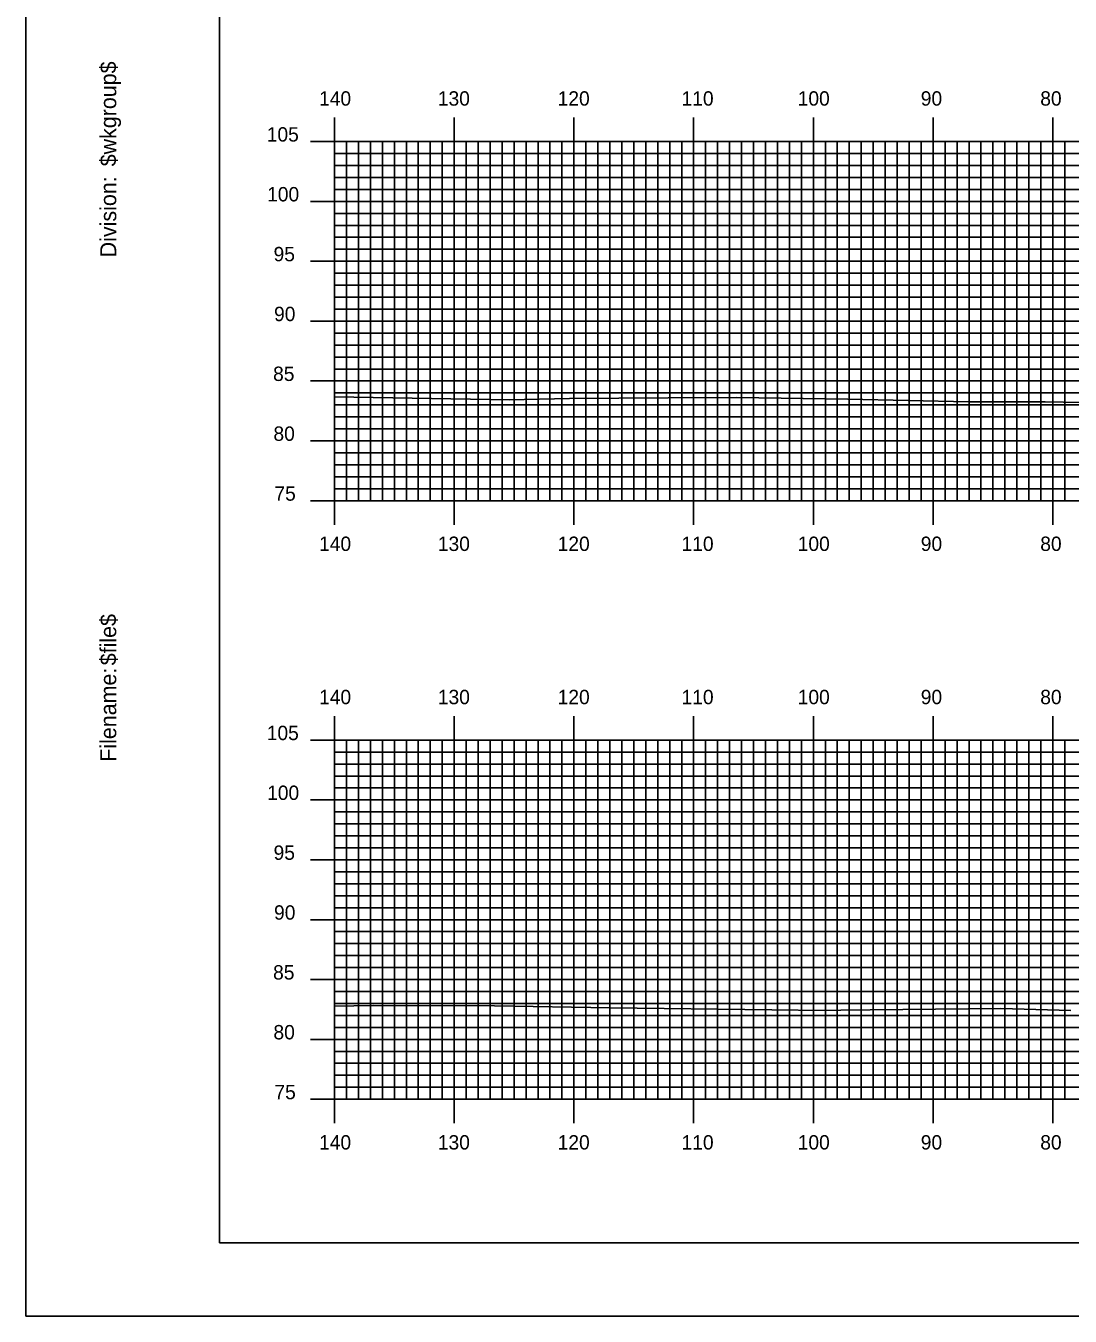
# Model space of a CAD drawing. Extents: x 1757856 to 1758199, y 442591 to 442811.
# Drawn here: x 1757855.8 to 1757943.1, y 442590.5 to 442698.3 of the extents above; entities that cross this region are included whole.
import ezdxf

# ---------------------------------------------------------------- set-up
doc = ezdxf.new("R2010")
doc.units = 0
for name, color, linetype in [('BORDER', 7, 'Continuous'), ('H_V ANNOTATION', 7, 'Continuous'), ('MAJOR', 7, 'Continuous'), ('MINOR', 7, 'Continuous'), ('PLOT BOUNDARY', 7, 'Continuous'), ('S_Roadway_Centerline', 7, 'Continuous')]:
    doc.layers.add(name, color=color, linetype=linetype)

msp = doc.modelspace()

# ---------------------------------------------------------------- linework, layer by layer
at = {"layer": 'BORDER'}
msp.add_lwpolyline([(1757872.02, 442596.67), (1758192.02, 442596.67), (1758192.02, 442806.67), (1757872.02, 442806.67)], close=True, dxfattribs=at)
at = {"layer": 'MAJOR'}
for p, q in [((1757881.62, 442690.67), (1757881.62, 442688.67)), ((1757891.62, 442690.67), (1757891.62, 442688.67)), ((1757901.62, 442690.67), (1757901.62, 442688.67)), ((1757911.62, 442690.67), (1757911.62, 442688.67)), ((1757921.62, 442690.67), (1757921.62, 442688.67)), ((1757931.62, 442690.67), (1757931.62, 442688.67)), ((1757941.62, 442690.67), (1757941.62, 442688.67)), ((1757879.62, 442688.67), (1757881.62, 442688.67)), ((1757881.62, 442688.67), (1758161.62, 442688.67)), ((1757881.62, 442658.67), (1757881.62, 442688.67)), ((1757881.62, 442658.67), (1757881.62, 442688.67)), ((1757881.62, 442688.67), (1758161.62, 442688.67)), ((1757891.62, 442658.67), (1757891.62, 442688.67)), ((1757901.62, 442658.67), (1757901.62, 442688.67)), ((1757911.62, 442658.67), (1757911.62, 442688.67)), ((1757921.62, 442658.67), (1757921.62, 442688.67)), ((1757931.62, 442658.67), (1757931.62, 442688.67)), ((1757941.62, 442658.67), (1757941.62, 442688.67)), ((1757879.62, 442683.67), (1757881.62, 442683.67)), ((1757881.62, 442683.67), (1758161.62, 442683.67)), ((1757879.62, 442678.67), (1757881.62, 442678.67)), ((1757881.62, 442678.67), (1758161.62, 442678.67)), ((1757879.62, 442673.67), (1757881.62, 442673.67)), ((1757881.62, 442673.67), (1758161.62, 442673.67)), ((1757879.62, 442668.67), (1757881.62, 442668.67)), ((1757881.62, 442668.67), (1758161.62, 442668.67)), ((1757879.62, 442663.67), (1757881.62, 442663.67)), ((1757881.62, 442663.67), (1758161.62, 442663.67)), ((1757879.62, 442658.67), (1757881.62, 442658.67)), ((1757881.62, 442658.67), (1758161.62, 442658.67)), ((1757881.62, 442658.67), (1758161.62, 442658.67)), ((1757881.62, 442656.66), (1757881.62, 442658.67)), ((1757891.62, 442656.66), (1757891.62, 442658.67)), ((1757901.62, 442656.66), (1757901.62, 442658.67)), ((1757911.62, 442656.66), (1757911.62, 442658.67)), ((1757921.62, 442656.66), (1757921.62, 442658.67)), ((1757931.62, 442656.66), (1757931.62, 442658.67)), ((1757941.62, 442656.66), (1757941.62, 442658.67)), ((1757881.62, 442640.67), (1757881.62, 442638.67)), ((1757891.62, 442640.67), (1757891.62, 442638.67)), ((1757901.62, 442640.67), (1757901.62, 442638.67)), ((1757911.62, 442640.67), (1757911.62, 442638.67)), ((1757921.62, 442640.67), (1757921.62, 442638.67)), ((1757931.62, 442640.67), (1757931.62, 442638.67)), ((1757941.62, 442640.67), (1757941.62, 442638.67)), ((1757879.62, 442638.67), (1757881.62, 442638.67)), ((1757881.62, 442638.67), (1758161.62, 442638.67)), ((1757881.62, 442608.67), (1757881.62, 442638.67)), ((1757881.62, 442608.67), (1757881.62, 442638.67)), ((1757881.62, 442638.67), (1758161.62, 442638.67)), ((1757891.62, 442608.67), (1757891.62, 442638.67)), ((1757901.62, 442608.67), (1757901.62, 442638.67)), ((1757911.62, 442608.67), (1757911.62, 442638.67)), ((1757921.62, 442608.67), (1757921.62, 442638.67)), ((1757931.62, 442608.67), (1757931.62, 442638.67)), ((1757941.62, 442608.67), (1757941.62, 442638.67)), ((1757879.62, 442633.67), (1757881.62, 442633.67)), ((1757881.62, 442633.67), (1758161.62, 442633.67)), ((1757879.62, 442628.67), (1757881.62, 442628.67)), ((1757881.62, 442628.67), (1758161.62, 442628.67)), ((1757879.62, 442623.67), (1757881.62, 442623.67)), ((1757881.62, 442623.67), (1758161.62, 442623.67)), ((1757879.62, 442618.67), (1757881.62, 442618.67)), ((1757881.62, 442618.67), (1758161.62, 442618.67)), ((1757879.62, 442613.67), (1757881.62, 442613.67)), ((1757881.62, 442613.67), (1758161.62, 442613.67)), ((1757879.62, 442608.67), (1757881.62, 442608.67)), ((1757881.62, 442608.67), (1758161.62, 442608.67)), ((1757881.62, 442608.67), (1758161.62, 442608.67)), ((1757881.62, 442606.66), (1757881.62, 442608.67)), ((1757891.62, 442606.66), (1757891.62, 442608.67)), ((1757901.62, 442606.66), (1757901.62, 442608.67)), ((1757911.62, 442606.66), (1757911.62, 442608.67)), ((1757921.62, 442606.66), (1757921.62, 442608.67)), ((1757931.62, 442606.66), (1757931.62, 442608.67)), ((1757941.62, 442606.66), (1757941.62, 442608.67))]:
    msp.add_line(p, q, dxfattribs=at)
at = {"layer": 'MINOR'}
for p, q in [((1757882.62, 442658.67), (1757882.62, 442688.67)), ((1757883.62, 442658.67), (1757883.62, 442688.67)), ((1757884.62, 442658.67), (1757884.62, 442688.67)), ((1757885.62, 442658.67), (1757885.62, 442688.67)), ((1757886.62, 442658.67), (1757886.62, 442688.67)), ((1757887.62, 442658.67), (1757887.62, 442688.67)), ((1757888.62, 442658.67), (1757888.62, 442688.67)), ((1757889.62, 442658.67), (1757889.62, 442688.67)), ((1757890.62, 442658.67), (1757890.62, 442688.67)), ((1757892.62, 442658.67), (1757892.62, 442688.67)), ((1757893.62, 442658.67), (1757893.62, 442688.67)), ((1757894.62, 442658.67), (1757894.62, 442688.67)), ((1757895.62, 442658.67), (1757895.62, 442688.67)), ((1757896.62, 442658.67), (1757896.62, 442688.67)), ((1757897.62, 442658.67), (1757897.62, 442688.67)), ((1757898.62, 442658.67), (1757898.62, 442688.67)), ((1757899.62, 442658.67), (1757899.62, 442688.67)), ((1757900.62, 442658.67), (1757900.62, 442688.67)), ((1757902.62, 442658.67), (1757902.62, 442688.67)), ((1757903.62, 442658.67), (1757903.62, 442688.67)), ((1757904.62, 442658.67), (1757904.62, 442688.67)), ((1757905.62, 442658.67), (1757905.62, 442688.67)), ((1757906.62, 442658.67), (1757906.62, 442688.67)), ((1757907.62, 442658.67), (1757907.62, 442688.67)), ((1757908.62, 442658.67), (1757908.62, 442688.67)), ((1757909.62, 442658.67), (1757909.62, 442688.67)), ((1757910.62, 442658.67), (1757910.62, 442688.67)), ((1757912.62, 442658.67), (1757912.62, 442688.67)), ((1757913.62, 442658.67), (1757913.62, 442688.67)), ((1757914.62, 442658.67), (1757914.62, 442688.67)), ((1757915.62, 442658.67), (1757915.62, 442688.67)), ((1757916.62, 442658.67), (1757916.62, 442688.67)), ((1757917.62, 442658.67), (1757917.62, 442688.67)), ((1757918.62, 442658.67), (1757918.62, 442688.67)), ((1757919.62, 442658.67), (1757919.62, 442688.67)), ((1757920.62, 442658.67), (1757920.62, 442688.67)), ((1757922.62, 442658.67), (1757922.62, 442688.67)), ((1757923.62, 442658.67), (1757923.62, 442688.67)), ((1757924.62, 442658.67), (1757924.62, 442688.67)), ((1757925.62, 442658.67), (1757925.62, 442688.67)), ((1757926.62, 442658.67), (1757926.62, 442688.67)), ((1757927.62, 442658.67), (1757927.62, 442688.67)), ((1757928.62, 442658.67), (1757928.62, 442688.67)), ((1757929.62, 442658.67), (1757929.62, 442688.67)), ((1757930.62, 442658.67), (1757930.62, 442688.67)), ((1757932.62, 442658.67), (1757932.62, 442688.67)), ((1757933.62, 442658.67), (1757933.62, 442688.67)), ((1757934.62, 442658.67), (1757934.62, 442688.67)), ((1757935.62, 442658.67), (1757935.62, 442688.67)), ((1757936.62, 442658.67), (1757936.62, 442688.67)), ((1757937.62, 442658.67), (1757937.62, 442688.67)), ((1757938.62, 442658.67), (1757938.62, 442688.67)), ((1757939.62, 442658.67), (1757939.62, 442688.67)), ((1757940.62, 442658.67), (1757940.62, 442688.67)), ((1757942.62, 442658.67), (1757942.62, 442688.67)), ((1757881.62, 442687.67), (1758161.62, 442687.67)), ((1757881.62, 442687.67), (1757883.63, 442687.67)), ((1757881.62, 442686.67), (1758161.62, 442686.67)), ((1757881.62, 442686.67), (1757883.63, 442686.67)), ((1757881.62, 442685.67), (1758161.62, 442685.67)), ((1757881.62, 442685.67), (1757883.63, 442685.67)), ((1757881.62, 442684.67), (1758161.62, 442684.67)), ((1757881.62, 442684.67), (1757883.63, 442684.67)), ((1757881.62, 442682.67), (1758161.62, 442682.67)), ((1757881.62, 442682.67), (1757883.63, 442682.67)), ((1757881.62, 442681.67), (1758161.62, 442681.67)), ((1757881.62, 442681.67), (1757883.63, 442681.67)), ((1757881.62, 442680.67), (1758161.62, 442680.67)), ((1757881.62, 442680.67), (1757883.63, 442680.67)), ((1757881.62, 442679.67), (1758161.62, 442679.67)), ((1757881.62, 442679.67), (1757883.63, 442679.67)), ((1757881.62, 442677.67), (1758161.62, 442677.67)), ((1757881.62, 442677.67), (1757883.63, 442677.67)), ((1757881.62, 442676.67), (1758161.62, 442676.67)), ((1757881.62, 442676.67), (1757883.63, 442676.67)), ((1757881.62, 442675.67), (1758161.62, 442675.67)), ((1757881.62, 442675.67), (1757883.63, 442675.67)), ((1757881.62, 442674.67), (1758161.62, 442674.67)), ((1757881.62, 442674.67), (1757883.63, 442674.67)), ((1757881.62, 442672.67), (1758161.62, 442672.67)), ((1757881.62, 442672.67), (1757883.63, 442672.67)), ((1757881.62, 442671.67), (1758161.62, 442671.67)), ((1757881.62, 442671.67), (1757883.63, 442671.67)), ((1757881.62, 442670.67), (1758161.62, 442670.67)), ((1757881.62, 442670.67), (1757883.63, 442670.67)), ((1757881.62, 442669.67), (1758161.62, 442669.67)), ((1757881.62, 442669.67), (1757883.63, 442669.67)), ((1757881.62, 442667.67), (1758161.62, 442667.67)), ((1757881.62, 442667.67), (1757883.63, 442667.67)), ((1757881.62, 442666.67), (1758161.62, 442666.67)), ((1757881.62, 442666.67), (1757883.63, 442666.67)), ((1757881.62, 442665.67), (1758161.62, 442665.67)), ((1757881.62, 442665.67), (1757883.63, 442665.67)), ((1757881.62, 442664.67), (1758161.62, 442664.67)), ((1757881.62, 442664.67), (1757883.63, 442664.67)), ((1757881.62, 442662.67), (1758161.62, 442662.67)), ((1757881.62, 442662.67), (1757883.63, 442662.67)), ((1757881.62, 442661.67), (1758161.62, 442661.67)), ((1757881.62, 442661.67), (1757883.63, 442661.67)), ((1757881.62, 442660.67), (1758161.62, 442660.67)), ((1757881.62, 442660.67), (1757883.63, 442660.67)), ((1757881.62, 442659.67), (1758161.62, 442659.67)), ((1757881.62, 442659.67), (1757883.63, 442659.67)), ((1757882.62, 442608.67), (1757882.62, 442638.67)), ((1757883.62, 442608.67), (1757883.62, 442638.67)), ((1757884.62, 442608.67), (1757884.62, 442638.67)), ((1757885.62, 442608.67), (1757885.62, 442638.67)), ((1757886.62, 442608.67), (1757886.62, 442638.67)), ((1757887.62, 442608.67), (1757887.62, 442638.67)), ((1757888.62, 442608.67), (1757888.62, 442638.67)), ((1757889.62, 442608.67), (1757889.62, 442638.67)), ((1757890.62, 442608.67), (1757890.62, 442638.67)), ((1757892.62, 442608.67), (1757892.62, 442638.67)), ((1757893.62, 442608.67), (1757893.62, 442638.67)), ((1757894.62, 442608.67), (1757894.62, 442638.67)), ((1757895.62, 442608.67), (1757895.62, 442638.67)), ((1757896.62, 442608.67), (1757896.62, 442638.67)), ((1757897.62, 442608.67), (1757897.62, 442638.67)), ((1757898.62, 442608.67), (1757898.62, 442638.67)), ((1757899.62, 442608.67), (1757899.62, 442638.67)), ((1757900.62, 442608.67), (1757900.62, 442638.67)), ((1757902.62, 442608.67), (1757902.62, 442638.67)), ((1757903.62, 442608.67), (1757903.62, 442638.67)), ((1757904.62, 442608.67), (1757904.62, 442638.67)), ((1757905.62, 442608.67), (1757905.62, 442638.67)), ((1757906.62, 442608.67), (1757906.62, 442638.67)), ((1757907.62, 442608.67), (1757907.62, 442638.67)), ((1757908.62, 442608.67), (1757908.62, 442638.67)), ((1757909.62, 442608.67), (1757909.62, 442638.67)), ((1757910.62, 442608.67), (1757910.62, 442638.67)), ((1757912.62, 442608.67), (1757912.62, 442638.67)), ((1757913.62, 442608.67), (1757913.62, 442638.67)), ((1757914.62, 442608.67), (1757914.62, 442638.67)), ((1757915.62, 442608.67), (1757915.62, 442638.67)), ((1757916.62, 442608.67), (1757916.62, 442638.67)), ((1757917.62, 442608.67), (1757917.62, 442638.67)), ((1757918.62, 442608.67), (1757918.62, 442638.67)), ((1757919.62, 442608.67), (1757919.62, 442638.67)), ((1757920.62, 442608.67), (1757920.62, 442638.67)), ((1757922.62, 442608.67), (1757922.62, 442638.67)), ((1757923.62, 442608.67), (1757923.62, 442638.67)), ((1757924.62, 442608.67), (1757924.62, 442638.67)), ((1757925.62, 442608.67), (1757925.62, 442638.67)), ((1757926.62, 442608.67), (1757926.62, 442638.67)), ((1757927.62, 442608.67), (1757927.62, 442638.67)), ((1757928.62, 442608.67), (1757928.62, 442638.67)), ((1757929.62, 442608.67), (1757929.62, 442638.67)), ((1757930.62, 442608.67), (1757930.62, 442638.67)), ((1757932.62, 442608.67), (1757932.62, 442638.67)), ((1757933.62, 442608.67), (1757933.62, 442638.67)), ((1757934.62, 442608.67), (1757934.62, 442638.67)), ((1757935.62, 442608.67), (1757935.62, 442638.67)), ((1757936.62, 442608.67), (1757936.62, 442638.67)), ((1757937.62, 442608.67), (1757937.62, 442638.67)), ((1757938.62, 442608.67), (1757938.62, 442638.67)), ((1757939.62, 442608.67), (1757939.62, 442638.67)), ((1757940.62, 442608.67), (1757940.62, 442638.67)), ((1757942.62, 442608.67), (1757942.62, 442638.67)), ((1757881.62, 442637.67), (1758161.62, 442637.67)), ((1757881.62, 442637.67), (1757883.63, 442637.67)), ((1757881.62, 442636.67), (1758161.62, 442636.67)), ((1757881.62, 442636.67), (1757883.63, 442636.67)), ((1757881.62, 442635.67), (1758161.62, 442635.67)), ((1757881.62, 442635.67), (1757883.63, 442635.67)), ((1757881.62, 442634.67), (1758161.62, 442634.67)), ((1757881.62, 442634.67), (1757883.63, 442634.67)), ((1757881.62, 442632.67), (1758161.62, 442632.67)), ((1757881.62, 442632.67), (1757883.63, 442632.67)), ((1757881.62, 442631.67), (1758161.62, 442631.67)), ((1757881.62, 442631.67), (1757883.63, 442631.67)), ((1757881.62, 442630.67), (1758161.62, 442630.67)), ((1757881.62, 442630.67), (1757883.63, 442630.67)), ((1757881.62, 442629.67), (1758161.62, 442629.67)), ((1757881.62, 442629.67), (1757883.63, 442629.67)), ((1757881.62, 442627.67), (1758161.62, 442627.67)), ((1757881.62, 442627.67), (1757883.63, 442627.67)), ((1757881.62, 442626.67), (1758161.62, 442626.67)), ((1757881.62, 442626.67), (1757883.63, 442626.67)), ((1757881.62, 442625.67), (1758161.62, 442625.67)), ((1757881.62, 442625.67), (1757883.63, 442625.67)), ((1757881.62, 442624.67), (1758161.62, 442624.67)), ((1757881.62, 442624.67), (1757883.63, 442624.67)), ((1757881.62, 442622.67), (1758161.62, 442622.67)), ((1757881.62, 442622.67), (1757883.63, 442622.67)), ((1757881.62, 442621.67), (1758161.62, 442621.67)), ((1757881.62, 442621.67), (1757883.63, 442621.67)), ((1757881.62, 442620.67), (1758161.62, 442620.67)), ((1757881.62, 442620.67), (1757883.63, 442620.67)), ((1757881.62, 442619.67), (1758161.62, 442619.67)), ((1757881.62, 442619.67), (1757883.63, 442619.67)), ((1757881.62, 442617.67), (1758161.62, 442617.67)), ((1757881.62, 442617.67), (1757883.63, 442617.67)), ((1757881.62, 442616.67), (1758161.62, 442616.67)), ((1757881.62, 442616.67), (1757883.63, 442616.67)), ((1757881.62, 442615.67), (1758161.62, 442615.67)), ((1757881.62, 442615.67), (1757883.63, 442615.67)), ((1757881.62, 442614.67), (1758161.62, 442614.67)), ((1757881.62, 442614.67), (1757883.63, 442614.67)), ((1757881.62, 442612.67), (1758161.62, 442612.67)), ((1757881.62, 442612.67), (1757883.63, 442612.67)), ((1757881.62, 442611.67), (1758161.62, 442611.67)), ((1757881.62, 442611.67), (1757883.63, 442611.67)), ((1757881.62, 442610.67), (1758161.62, 442610.67)), ((1757881.62, 442610.67), (1757883.63, 442610.67)), ((1757881.62, 442609.67), (1758161.62, 442609.67)), ((1757881.62, 442609.67), (1757883.63, 442609.67))]:
    msp.add_line(p, q, dxfattribs=at)
at = {"layer": 'PLOT BOUNDARY'}
msp.add_lwpolyline([(1757855.84, 442590.55), (1758195.84, 442590.55), (1758195.84, 442810.55), (1757855.84, 442810.55)], close=True, dxfattribs=at)
at = {"layer": 'S_Roadway_Centerline'}
for points in [[(1757881.62, 442667.35), (1757896.2, 442667.09), (1757901.25, 442667.2), (1757909.48, 442667.26), (1757915.2, 442667.28), (1757924.5, 442667.16), (1757934.57, 442666.94), (1757940.97, 442666.92), (1757948.63, 442666.8)], [(1757881.62, 442616.44), (1757884.86, 442616.5), (1757894.98, 442616.47), (1757904.65, 442616.3), (1757918.14, 442616.14), (1757922.58, 442616.07), (1757923.92, 442616.12), (1757926.36, 442616.13), (1757937.27, 442616.26), (1757943.12, 442616.08)]]:
    msp.add_lwpolyline(points, dxfattribs=at)

# ---------------------------------------------------------------- texts
at = {"layer": 'BORDER'}
for s, p in [('$wkgroup$', (1757863.39, 442686.6)), ('$wkgroup$', (1757863.39, 442686.6)), ('Division:', (1757863.39, 442679)), ('Division:', (1757863.39, 442679)), ('$file$', (1757863.39, 442644.92)), ('$file$', (1757863.39, 442644.92)), ('Filename:', (1757863.39, 442636.86)), ('Filename:', (1757863.39, 442636.86))]:
    msp.add_text(s, height=1.339, rotation=90, dxfattribs=at).set_placement(p)
at = {"layer": 'H_V ANNOTATION'}
for s, p in [('140', (1757880.33, 442691.67)), ('130', (1757890.25, 442691.67)), ('120', (1757900.26, 442691.67)), ('110', (1757910.61, 442691.67)), ('100', (1757920.31, 442691.67)), ('90', (1757930.59, 442691.67)), ('80', (1757940.57, 442691.67)), ('105', (1757875.96, 442688.67)), ('100', (1757875.99, 442683.67)), ('95', (1757876.53, 442678.67)), ('90', (1757876.57, 442673.67)), ('85', (1757876.49, 442668.67)), ('80', (1757876.52, 442663.67)), ('75', (1757876.6, 442658.67)), ('140', (1757880.33, 442654.47)), ('130', (1757890.25, 442654.47)), ('120', (1757900.26, 442654.47)), ('110', (1757910.61, 442654.47)), ('100', (1757920.31, 442654.47)), ('90', (1757930.59, 442654.47)), ('80', (1757940.57, 442654.47)), ('140', (1757880.33, 442641.67)), ('130', (1757890.25, 442641.67)), ('120', (1757900.26, 442641.67)), ('110', (1757910.61, 442641.67)), ('100', (1757920.31, 442641.67)), ('90', (1757930.59, 442641.67)), ('80', (1757940.57, 442641.67)), ('105', (1757875.96, 442638.67)), ('100', (1757875.99, 442633.67)), ('95', (1757876.53, 442628.67)), ('90', (1757876.57, 442623.67)), ('85', (1757876.49, 442618.67)), ('80', (1757876.52, 442613.67)), ('75', (1757876.6, 442608.67)), ('140', (1757880.33, 442604.47)), ('130', (1757890.25, 442604.47)), ('120', (1757900.26, 442604.47)), ('110', (1757910.61, 442604.47)), ('100', (1757920.31, 442604.47)), ('90', (1757930.59, 442604.47)), ('80', (1757940.57, 442604.47))]:
    msp.add_text(s, height=1.2, dxfattribs=at).set_placement(p)
at = {"layer": 'MAJOR'}
for p in [(1757881.61, 442658.67), (1757881.61, 442608.67)]:
    msp.add_text('-', height=0.012, dxfattribs=at).set_placement(p)

doc.saveas('drawing.dxf')
